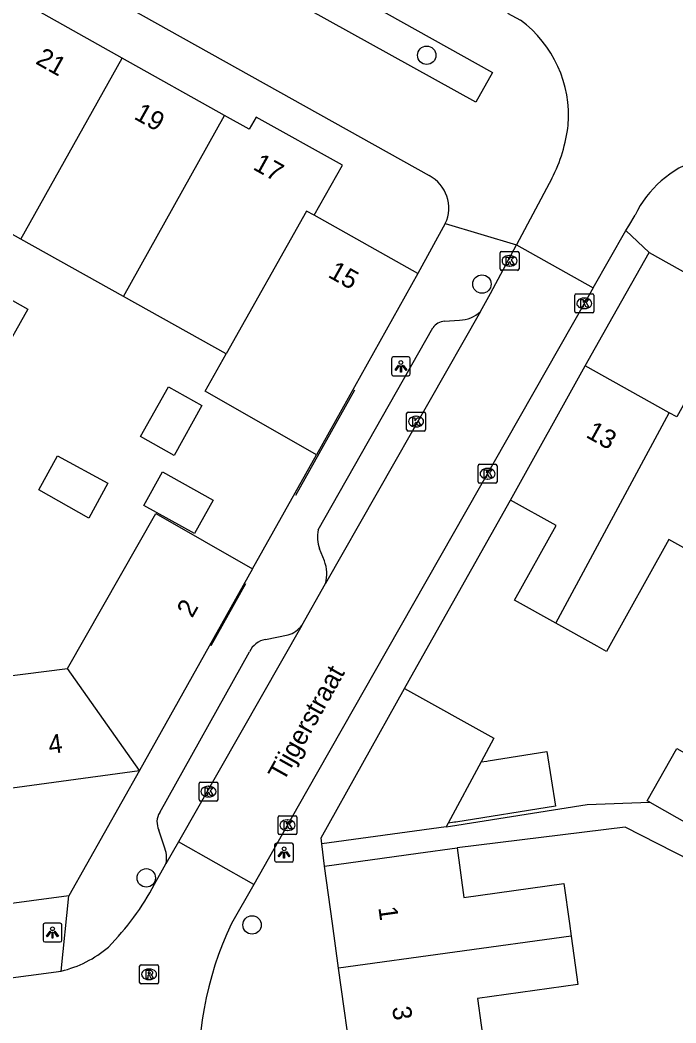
# Model space of a CAD drawing. Extents: x 163150 to 163546, y 380933 to 381635.
# Drawn here: x 163384.3 to 163419, y 381494.7 to 381547.9 of the extents above; entities that cross this region are included whole.
import ezdxf

# ---------------------------------------------------------------- set-up
doc = ezdxf.new("R2010")
doc.units = 0
for name, color, linetype in [('IMGEO_Boom', 7, 'Continuous'), ('IMGEO_Kolk', 7, 'Continuous'), ('IMGEO_Lichtpunt', 7, 'Continuous'), ('IMGEO_Muur', 7, 'Continuous'), ('IMGEO_Openbare_ruimte_label', 7, 'Continuous'), ('IMGEO_Pand', 7, 'Continuous'), ('IMGEO_Pand_nummerreeks', 7, 'Continuous'), ('IMGEO_Rijbaan_lokaal_open', 7, 'Continuous'), ('IMGEO_Rioolput', 7, 'Continuous'), ('IMGEO_Voetpad_open', 7, 'Continuous')]:
    doc.layers.add(name, color=color, linetype=linetype)

msp = doc.modelspace()

# ---------------------------------------------------------------- linework, layer by layer
at = {"layer": 'IMGEO_Boom'}
for centre in [(163405.837, 381545.994), (163408.762, 381533.873), (163390.984, 381502.417), (163396.588, 381499.924)]:
    msp.add_circle(centre, 0.489, dxfattribs=at)
at = {"layer": 'IMGEO_Kolk'}
for p, q in [((163409.724, 381534.676), (163409.724, 381535.528)), ((163409.799, 381535.602), (163410.651, 381535.602)), ((163410.212, 381535.382), (163410.237, 381535.382)), ((163410.725, 381535.528), (163410.725, 381534.676)), ((163410.651, 381534.602), (163409.799, 381534.602)), ((163410.235, 381534.822), (163410.21, 381534.822)), ((163413.683, 381532.426), (163413.683, 381533.278)), ((163413.758, 381533.352), (163414.61, 381533.352)), ((163414.171, 381533.132), (163414.196, 381533.132)), ((163414.684, 381533.278), (163414.684, 381532.426)), ((163414.194, 381532.572), (163414.169, 381532.572)), ((163414.61, 381532.352), (163413.758, 381532.352)), ((163404.772, 381526.162), (163404.772, 381527.014)), ((163404.847, 381527.088), (163405.699, 381527.088)), ((163405.26, 381526.868), (163405.285, 381526.868)), ((163405.773, 381527.014), (163405.773, 381526.162)), ((163405.699, 381526.088), (163404.847, 381526.088)), ((163405.283, 381526.308), (163405.258, 381526.308)), ((163408.561, 381523.401), (163408.561, 381524.253)), ((163408.636, 381524.327), (163409.488, 381524.327)), ((163409.049, 381524.107), (163409.074, 381524.107)), ((163409.562, 381524.253), (163409.562, 381523.401)), ((163409.072, 381523.547), (163409.047, 381523.547)), ((163409.488, 381523.327), (163408.636, 381523.327)), ((163393.856, 381507.487), (163394.708, 381507.487)), ((163393.781, 381506.561), (163393.781, 381507.413)), ((163394.269, 381507.267), (163394.294, 381507.267)), ((163394.782, 381507.413), (163394.782, 381506.561)), ((163394.708, 381506.487), (163393.856, 381506.487)), ((163394.292, 381506.707), (163394.267, 381506.707)), ((163397.961, 381504.782), (163397.961, 381505.634)), ((163398.036, 381505.708), (163398.888, 381505.708)), ((163398.449, 381505.488), (163398.474, 381505.488)), ((163398.962, 381505.634), (163398.962, 381504.782)), ((163398.472, 381504.928), (163398.447, 381504.928)), ((163398.888, 381504.708), (163398.036, 381504.708))]:
    msp.add_line(p, q, dxfattribs=at)
for points in [[(163409.724, 381534.676), (163409.724, 381535.528)], [(163409.799, 381535.602), (163410.651, 381535.602)], [(163410.045, 381535.302), (163410.168, 381535.302), (163410.168, 381535.151), (163410.298, 381535.302), (163410.462, 381535.302), (163410.316, 381535.151), (163410.469, 381534.902), (163410.317, 381534.902), (163410.232, 381535.066), (163410.168, 381534.999), (163410.168, 381534.902), (163410.045, 381534.902), (163410.045, 381535.302)], [(163410.725, 381535.528), (163410.725, 381534.676)], [(163410.651, 381534.602), (163409.799, 381534.602)], [(163413.683, 381532.426), (163413.683, 381533.278)], [(163413.758, 381533.352), (163414.61, 381533.352)], [(163414.004, 381533.052), (163414.127, 381533.052), (163414.127, 381532.901), (163414.257, 381533.052), (163414.421, 381533.052), (163414.275, 381532.901), (163414.428, 381532.652), (163414.276, 381532.652), (163414.191, 381532.816), (163414.127, 381532.749), (163414.127, 381532.652), (163414.004, 381532.652), (163414.004, 381533.052)], [(163414.684, 381533.278), (163414.684, 381532.426)], [(163414.61, 381532.352), (163413.758, 381532.352)], [(163404.772, 381526.162), (163404.772, 381527.014)], [(163404.847, 381527.088), (163405.699, 381527.088)], [(163405.093, 381526.788), (163405.216, 381526.788), (163405.216, 381526.637), (163405.346, 381526.788), (163405.51, 381526.788), (163405.364, 381526.637), (163405.517, 381526.388), (163405.365, 381526.388), (163405.28, 381526.552), (163405.216, 381526.485), (163405.216, 381526.388), (163405.093, 381526.388), (163405.093, 381526.788)], [(163405.773, 381527.014), (163405.773, 381526.162)], [(163405.699, 381526.088), (163404.847, 381526.088)], [(163408.561, 381523.401), (163408.561, 381524.253)], [(163408.636, 381524.327), (163409.488, 381524.327)], [(163408.882, 381524.027), (163409.005, 381524.027), (163409.005, 381523.876), (163409.135, 381524.027), (163409.299, 381524.027), (163409.153, 381523.876), (163409.306, 381523.627), (163409.154, 381523.627), (163409.069, 381523.791), (163409.005, 381523.724), (163409.005, 381523.627), (163408.882, 381523.627), (163408.882, 381524.027)], [(163409.562, 381524.253), (163409.562, 381523.401)], [(163409.488, 381523.327), (163408.636, 381523.327)], [(163393.856, 381507.487), (163394.708, 381507.487)], [(163393.781, 381506.561), (163393.781, 381507.413)], [(163394.102, 381507.187), (163394.225, 381507.187), (163394.225, 381507.036), (163394.355, 381507.187), (163394.519, 381507.187), (163394.373, 381507.036), (163394.526, 381506.787), (163394.374, 381506.787), (163394.289, 381506.951), (163394.225, 381506.884), (163394.225, 381506.787), (163394.102, 381506.787), (163394.102, 381507.187)], [(163394.782, 381507.413), (163394.782, 381506.561)], [(163394.708, 381506.487), (163393.856, 381506.487)], [(163397.961, 381504.782), (163397.961, 381505.634)], [(163398.036, 381505.708), (163398.888, 381505.708)], [(163398.282, 381505.408), (163398.405, 381505.408), (163398.405, 381505.257), (163398.535, 381505.408), (163398.699, 381505.408), (163398.553, 381505.257), (163398.706, 381505.008), (163398.554, 381505.008), (163398.469, 381505.172), (163398.405, 381505.105), (163398.405, 381505.008), (163398.282, 381505.008), (163398.282, 381505.408)], [(163398.962, 381505.634), (163398.962, 381504.782)], [(163398.888, 381504.708), (163398.036, 381504.708)]]:
    msp.add_lwpolyline(points, dxfattribs=at)
for centre, start, end in [((163409.801, 381535.526), 91.552, 178.448), ((163409.801, 381535.526), 91.552, 178.448), ((163410.649, 381535.526), 1.552, 88.448), ((163410.649, 381535.526), 1.552, 88.448), ((163409.801, 381534.678), 181.552, 268.448), ((163409.801, 381534.678), 181.552, 268.448), ((163410.649, 381534.678), 271.552, 358.448), ((163410.649, 381534.678), 271.552, 358.448), ((163413.76, 381533.276), 91.552, 178.448), ((163413.76, 381533.276), 91.552, 178.448), ((163414.608, 381533.276), 1.552, 88.448), ((163414.608, 381533.276), 1.552, 88.448), ((163413.76, 381532.428), 181.552, 268.448), ((163413.76, 381532.428), 181.552, 268.448), ((163414.608, 381532.428), 271.552, 358.448), ((163414.608, 381532.428), 271.552, 358.448), ((163404.849, 381527.012), 91.552, 178.448), ((163404.849, 381527.012), 91.552, 178.448), ((163405.697, 381527.012), 1.552, 88.448), ((163405.697, 381527.012), 1.552, 88.448), ((163404.849, 381526.164), 181.552, 268.448), ((163404.849, 381526.164), 181.552, 268.448), ((163405.697, 381526.164), 271.552, 358.448), ((163405.697, 381526.164), 271.552, 358.448), ((163408.638, 381524.251), 91.552, 178.448), ((163408.638, 381524.251), 91.552, 178.448), ((163409.486, 381524.251), 1.552, 88.448), ((163409.486, 381524.251), 1.552, 88.448), ((163408.638, 381523.403), 181.552, 268.448), ((163408.638, 381523.403), 181.552, 268.448), ((163409.486, 381523.403), 271.552, 358.448), ((163409.486, 381523.403), 271.552, 358.448), ((163393.858, 381507.411), 91.552, 178.448), ((163393.858, 381507.411), 91.552, 178.448), ((163394.706, 381507.411), 1.552, 88.448), ((163394.706, 381507.411), 1.552, 88.448), ((163393.858, 381506.563), 181.552, 268.448), ((163393.858, 381506.563), 181.552, 268.448), ((163394.706, 381506.563), 271.552, 358.448), ((163394.706, 381506.563), 271.552, 358.448), ((163398.038, 381505.632), 91.552, 178.448), ((163398.038, 381505.632), 91.552, 178.448), ((163398.886, 381505.632), 1.552, 88.448), ((163398.886, 381505.632), 1.552, 88.448), ((163398.038, 381504.784), 181.552, 268.448), ((163398.038, 381504.784), 181.552, 268.448), ((163398.886, 381504.784), 271.552, 358.448), ((163398.886, 381504.784), 271.552, 358.448)]:
    msp.add_arc(centre, 0.0765, start, end, dxfattribs=at)
for centre, major_axis, ratio, start_param, end_param in [((163410.211, 381535.102), (-0.387, 0.002), 0.722429, 4.712389, 7.853982), ((163410.236, 381535.102), (-0.39, 0.002), 0.717154, 1.570796, 4.712389), ((163414.17, 381532.852), (-0.387, 0.002), 0.722429, 4.712389, 7.853982), ((163414.195, 381532.852), (-0.39, 0.002), 0.717154, 1.570796, 4.712389), ((163405.259, 381526.588), (-0.387, 0.002), 0.722429, 4.712389, 7.853982), ((163405.284, 381526.588), (-0.39, 0.002), 0.717154, 1.570796, 4.712389), ((163409.048, 381523.827), (-0.387, 0.002), 0.722429, 4.712389, 7.853982), ((163409.073, 381523.827), (-0.39, 0.002), 0.717154, 1.570796, 4.712389), ((163394.268, 381506.987), (-0.387, 0.002), 0.722429, 4.712389, 7.853982), ((163394.293, 381506.987), (-0.39, 0.002), 0.717154, 1.570796, 4.712389), ((163398.448, 381505.208), (-0.387, 0.002), 0.722429, 4.712389, 7.853982), ((163398.473, 381505.208), (-0.39, 0.002), 0.717154, 1.570796, 4.712389)]:
    msp.add_ellipse(centre, major_axis=major_axis, ratio=ratio, start_param=start_param, end_param=end_param, dxfattribs=at)
at = {"layer": 'IMGEO_Lichtpunt'}
for p, q in [((163403.972, 381529.922), (163403.972, 381529.115)), ((163403.972, 381529.922), (163403.972, 381529.115)), ((163404.874, 381530.017), (163404.066, 381530.017)), ((163404.874, 381530.017), (163404.066, 381530.017)), ((163404.968, 381529.115), (163404.968, 381529.922)), ((163404.968, 381529.115), (163404.968, 381529.922)), ((163404.066, 381529.021), (163404.874, 381529.021)), ((163404.066, 381529.021), (163404.874, 381529.021)), ((163397.783, 381504.159), (163397.783, 381503.352)), ((163397.783, 381504.159), (163397.783, 381503.352)), ((163398.685, 381504.254), (163397.877, 381504.254)), ((163398.685, 381504.254), (163397.877, 381504.254)), ((163398.779, 381503.352), (163398.779, 381504.159)), ((163398.779, 381503.352), (163398.779, 381504.159)), ((163397.877, 381503.258), (163398.685, 381503.258)), ((163397.877, 381503.258), (163398.685, 381503.258)), ((163385.518, 381499.924), (163385.518, 381499.117)), ((163385.518, 381499.924), (163385.518, 381499.117)), ((163386.42, 381500.019), (163385.612, 381500.019)), ((163386.42, 381500.019), (163385.612, 381500.019)), ((163386.514, 381499.117), (163386.514, 381499.924)), ((163386.514, 381499.117), (163386.514, 381499.924)), ((163385.612, 381499.023), (163386.42, 381499.023)), ((163385.612, 381499.023), (163386.42, 381499.023))]:
    msp.add_line(p, q, dxfattribs=at)
for points in [[(163404.346, 381529.586), (163404.385, 381529.558), (163404.197, 381529.296), (163404.159, 381529.323), (163404.346, 381529.586)], [(163404.448, 381529.538), (163404.495, 381529.538), (163404.495, 381529.216), (163404.448, 381529.216), (163404.448, 381529.538)], [(163404.558, 381529.558), (163404.596, 381529.585), (163404.783, 381529.323), (163404.744, 381529.295), (163404.558, 381529.558)], [(163398.157, 381503.823), (163398.196, 381503.795), (163398.008, 381503.533), (163397.97, 381503.56), (163398.157, 381503.823)], [(163398.259, 381503.775), (163398.306, 381503.775), (163398.306, 381503.453), (163398.259, 381503.453), (163398.259, 381503.775)], [(163398.369, 381503.795), (163398.407, 381503.822), (163398.594, 381503.56), (163398.555, 381503.532), (163398.369, 381503.795)], [(163385.892, 381499.588), (163385.931, 381499.56), (163385.743, 381499.298), (163385.705, 381499.325), (163385.892, 381499.588)], [(163385.994, 381499.54), (163386.041, 381499.54), (163386.041, 381499.218), (163385.994, 381499.218), (163385.994, 381499.54)], [(163386.104, 381499.56), (163386.142, 381499.587), (163386.329, 381499.325), (163386.29, 381499.297), (163386.104, 381499.56)]]:
    msp.add_lwpolyline(points, dxfattribs=at)
for centre in [(163404.471, 381529.72), (163398.282, 381503.957), (163386.017, 381499.722)]:
    msp.add_circle(centre, 0.0994, dxfattribs=at)
for centre, start, end in [((163404.066, 381529.922), 90, 180), ((163404.066, 381529.922), 90, 180), ((163404.874, 381529.922), 0, 90), ((163404.874, 381529.922), 0, 90), ((163404.066, 381529.115), 180, 270), ((163404.066, 381529.115), 180, 270), ((163404.874, 381529.115), 270, 0), ((163404.874, 381529.115), 270, 360), ((163397.877, 381504.159), 90, 180), ((163397.877, 381504.159), 90, 180), ((163398.685, 381504.159), 0, 90), ((163398.685, 381504.159), 0, 90), ((163397.877, 381503.352), 180, 270), ((163397.877, 381503.352), 180, 270), ((163398.685, 381503.352), 270, 0), ((163398.685, 381503.352), 270, 360), ((163385.612, 381499.924), 90, 180), ((163385.612, 381499.924), 90, 180), ((163386.42, 381499.924), 0, 90), ((163386.42, 381499.924), 0, 90), ((163385.612, 381499.117), 180, 270), ((163385.612, 381499.117), 180, 270), ((163386.42, 381499.117), 270, 0), ((163386.42, 381499.117), 270, 360)]:
    msp.add_arc(centre, 0.0946, start, end, dxfattribs=at)
at = {"layer": 'IMGEO_Muur'}
for points in [[(163398.9, 381522.691), (163402.034, 381528.266)], [(163405.156, 381513.335), (163410.272, 381522.434)], [(163394.422, 381514.725), (163396.264, 381518.003)]]:
    msp.add_lwpolyline(points, dxfattribs=at)
at = {"layer": 'IMGEO_Pand'}
for points in [[(163389.698, 381545.85), (163384.263, 381548.895)], [(163384.335, 381536.26), (163389.698, 381545.85)], [(163395.133, 381542.804), (163389.698, 381545.85)], [(163389.772, 381533.219), (163395.133, 381542.804)], [(163399.878, 381537.517), (163401.373, 381540.169), (163396.812, 381542.714), (163396.436, 381542.073), (163395.133, 381542.804)], [(163384.335, 381536.26), (163378.897, 381539.301)], [(163399.878, 381537.517), (163399.474, 381537.743), (163395.21, 381530.178)], [(163405.373, 381534.442), (163399.878, 381537.517)], [(163389.772, 381533.219), (163384.335, 381536.26)], [(163405.373, 381534.442), (163399.995, 381524.821)], [(163382.946, 381533.542), (163384.705, 381532.549), (163383.23, 381529.937), (163381.471, 381530.93)], [(163395.21, 381530.178), (163389.772, 381533.219)], [(163399.995, 381524.821), (163394.095, 381528.2), (163395.21, 381530.178)], [(163410.272, 381522.434), (163414.231, 381529.537)], [(163418.679, 381527.058), (163414.231, 381529.537)], [(163425.443, 381526.737), (163420.55, 381529.464), (163419.083, 381526.833), (163418.679, 381527.058)], [(163392.157, 381528.422), (163393.933, 381527.438), (163392.466, 381524.79), (163390.677, 381525.803), (163392.157, 381528.422)], [(163412.675, 381515.904), (163418.679, 381527.058)], [(163386.277, 381524.781), (163388.941, 381523.333), (163387.936, 381521.476), (163385.288, 381522.981), (163386.277, 381524.781)], [(163390.856, 381522.148), (163391.845, 381523.923), (163394.528, 381522.435), (163393.543, 381520.66), (163390.856, 381522.148)], [(163412.675, 381515.904), (163410.492, 381517.121), (163412.7, 381521.08), (163410.272, 381522.434)], [(163386.81, 381513.506), (163391.494, 381521.713), (163396.616, 381518.793)], [(163421.229, 381518.91), (163418.659, 381520.343), (163415.352, 381514.411), (163414.86, 381514.686), (163412.675, 381515.904)], [(163396.616, 381518.793), (163390.622, 381508.099)], [(163378.437, 381512.446), (163386.81, 381513.506)], [(163390.622, 381508.099), (163386.81, 381513.506)], [(163400.279, 381504.213), (163400.246, 381504.532), (163404.666, 381512.456)], [(163404.666, 381512.456), (163409.399, 381509.817), (163408.72, 381508.556)], [(163408.72, 381508.556), (163409.018, 381508.603), (163409.088, 381508.615), (163412.202, 381509.113), (163412.665, 381506.223), (163407.37, 381505.375), (163407.307, 381505.365), (163407.203, 381505.348), (163406.974, 381505.312)], [(163417.656, 381506.427), (163417.521, 381506.503), (163419.091, 381509.276), (163421.419, 381507.957)], [(163408.72, 381508.556), (163406.974, 381505.312)], [(163379.644, 381502.906), (163382.408, 381503.275), (163381.921, 381506.929), (163390.622, 381508.099)], [(163417.656, 381506.427), (163419.867, 381505.174)], [(163406.872, 381505.122), (163400.279, 381504.213)], [(163406.974, 381505.312), (163406.872, 381505.122)], [(163400.424, 381503.043), (163405.378, 381503.726), (163407.444, 381504.011)], [(163407.444, 381504.011), (163407.806, 381501.386), (163413.097, 381502.115), (163413.393, 381500), (163413.486, 381499.333)], [(163401.169, 381497.642), (163400.844, 381500), (163400.424, 381503.043)], [(163413.486, 381499.333), (163401.169, 381497.642)], [(163413.486, 381499.333), (163413.844, 381496.769), (163408.52, 381496.035), (163408.91, 381493.202)], [(163401.915, 381492.238), (163401.169, 381497.642)]]:
    msp.add_lwpolyline(points, dxfattribs=at)
at = {"layer": 'IMGEO_Rijbaan_lokaal_open'}
for points in [[(163410.118, 381548.234), (163410.806, 381547.858)], [(163412.47, 381539.47), (163410.599, 381535.956)], [(163416.384, 381536.72), (163416.546, 381536.957), (163416.871, 381537.519)], [(163414.654, 381533.678), (163416.384, 381536.72)], [(163408.677, 381532.42), (163409.219, 381533.373), (163410.599, 381535.956)], [(163410.599, 381535.956), (163414.654, 381533.678)], [(163414.654, 381533.678), (163414.262, 381532.989), (163403.04, 381513.257), (163402.013, 381511.452), (163400.059, 381508.016), (163399.031, 381506.208), (163396.678, 381502.07)], [(163408.677, 381532.42), (163400.477, 381518.009)], [(163399.217, 381515.793), (163400.477, 381518.009)], [(163399.217, 381515.793), (163392.697, 381504.335)], [(163392.697, 381504.335), (163392.026, 381503.156)], [(163396.678, 381502.07), (163392.697, 381504.335)], [(163391.416, 381502.077), (163392.026, 381503.156)], [(163396.678, 381502.07), (163395.5, 381500)], [(163382.807, 381497.014), (163382.998, 381497.011), (163386.472, 381497.48)]]:
    msp.add_lwpolyline(points, dxfattribs=at)
for centre, radius, start, end in [((163407.016, 381542.779), 6.337, 355.6466, 53.2708), ((163404.639, 381543.411), 8.767, 333.2821, 352.7033), ((163422.009, 381535.048), 5.702, 61.4772, 154.3223), ((163378.756, 381508.8), 14.335, 315.5111, 332.0291), ((163411.836, 381492.225), 18.092, 154.5483, 184.6632), ((163385.108, 381503.273), 5.952, 283.2481, 310.6101)]:
    msp.add_arc(centre, radius, start, end, dxfattribs=at)
at = {"layer": 'IMGEO_Rioolput'}
for p, q in [((163390.631, 381496.88), (163390.631, 381497.732)), ((163390.706, 381497.806), (163391.558, 381497.806)), ((163391.119, 381497.586), (163391.144, 381497.586)), ((163391.632, 381497.732), (163391.632, 381496.88)), ((163391.142, 381497.026), (163391.117, 381497.026)), ((163391.558, 381496.806), (163390.706, 381496.806))]:
    msp.add_line(p, q, dxfattribs=at)
for points in [[(163390.631, 381496.88), (163390.631, 381497.732)], [(163390.706, 381497.806), (163391.558, 381497.806)], [(163391.22, 381497.504), (163390.968, 381497.506), (163390.968, 381497.106)], [(163391.146, 381497.425), (163391.092, 381497.425), (163391.092, 381497.344)], [(163391.632, 381497.732), (163391.632, 381496.88)], [(163390.968, 381497.106), (163391.092, 381497.106), (163391.092, 381497.268), (163391.103, 381497.268)], [(163391.092, 381497.344), (163391.144, 381497.344)], [(163391.15, 381497.239), (163391.221, 381497.106), (163391.361, 381497.106), (163391.296, 381497.232)], [(163391.558, 381496.806), (163390.706, 381496.806)]]:
    msp.add_lwpolyline(points, dxfattribs=at)
for centre, radius, start, end in [((163390.708, 381497.73), 0.0765, 91.552, 178.448), ((163390.708, 381497.73), 0.0765, 91.552, 178.448), ((163391.152, 381497.329), 0.0964, 77.0061, 93.1865), ((163391.166, 381497.386), 0.0378, 276.6634, 79.6772), ((163391.219, 381497.394), 0.109, 350.3612, 89.416), ((163391.556, 381497.73), 0.0765, 1.552, 88.448), ((163391.556, 381497.73), 0.0765, 1.552, 88.448), ((163390.708, 381496.882), 0.0765, 181.552, 268.448), ((163390.708, 381496.882), 0.0765, 181.552, 268.448), ((163391.102, 381497.215), 0.0533, 26.0293, 88.6989), ((163391.128, 381497.533), 0.19, 274.7715, 282.9687), ((163391.217, 381497.394), 0.112, 277.5842, 350.9817), ((163391.201, 381497.179), 0.108, 29.5134, 73.7905), ((163391.556, 381496.882), 0.0765, 271.552, 358.448), ((163391.556, 381496.882), 0.0765, 271.552, 358.448)]:
    msp.add_arc(centre, radius, start, end, dxfattribs=at)
for centre, major_axis, ratio, start_param, end_param in [((163391.118, 381497.306), (-0.387, 0.002), 0.722429, 4.712389, 7.853982), ((163391.143, 381497.306), (-0.39, 0.002), 0.717154, 1.570796, 4.712389)]:
    msp.add_ellipse(centre, major_axis=major_axis, ratio=ratio, start_param=start_param, end_param=end_param, dxfattribs=at)
at = {"layer": 'IMGEO_Voetpad_open'}
for points in [[(163297.645, 381600.322), (163371.092, 381559.098), (163405.961, 381539.624)], [(163392.587, 381554.436), (163409.323, 381545.083), (163408.442, 381543.507), (163391.704, 381552.793), (163392.587, 381554.436)], [(163406.822, 381537.075), (163405.373, 381534.442)], [(163406.822, 381537.075), (163410.599, 381535.956)], [(163417.612, 381535.547), (163416.384, 381536.72)], [(163414.231, 381529.537), (163415.715, 381532.175), (163417.612, 381535.547)], [(163417.612, 381535.547), (163450.218, 381517.299), (163454.104, 381515.141)], [(163406.779, 381531.908), (163407.579, 381531.958)], [(163400.091, 381520.848), (163406.154, 381531.56)], [(163396.616, 381518.793), (163399.995, 381524.821)], [(163404.666, 381512.456), (163405.156, 381513.335), (163410.272, 381522.434)], [(163400.416, 381519.211), (163400.164, 381519.848)], [(163397.3, 381515.05), (163398.491, 381515.293)], [(163391.695, 381505.878), (163396.445, 381514.395)], [(163390.622, 381508.099), (163386.878, 381501.46)], [(163406.872, 381505.122), (163407.094, 381505.153), (163414.331, 381506.299), (163417.656, 381506.427)], [(163391.925, 381504.1), (163391.651, 381504.952)], [(163422.267, 381503.814), (163421.576, 381502.441), (163416.346, 381505.106), (163407.444, 381504.011)], [(163400.424, 381503.043), (163400.279, 381504.213)], [(163386.878, 381501.46), (163323.846, 381493.024)], [(163386.472, 381497.48), (163386.878, 381501.46)]]:
    msp.add_lwpolyline(points, dxfattribs=at)
for centre, radius, start, end in [((163405.063, 381537.901), 1.943, 334.8576, 62.4702), ((163407.491, 381533.704), 1.748, 272.8965, 312.7428), ((163406.875, 381531), 0.913, 96.0582, 142.1599), ((163401.659, 381520.46), 1.615, 166.0949, 202.2555), ((163398.581, 381518.515), 1.963, 345.0495, 20.7609), ((163398.137, 381516.585), 1.339, 285.3429, 323.7679), ((163397.524, 381513.872), 1.199, 100.7741, 154.1361), ((163392.49, 381505.376), 0.941, 147.7537, 206.8055), ((163390.557, 381503.476), 1.503, 347.6991, 24.5148)]:
    msp.add_arc(centre, radius, start, end, dxfattribs=at)

# ---------------------------------------------------------------- texts
at = {"layer": 'IMGEO_Openbare_ruimte_label'}
msp.add_text('Tijgerstraat', height=1, rotation=60.7172, dxfattribs=at).set_placement((163398.252, 381507.467))
at = {"layer": 'IMGEO_Pand_nummerreeks'}
for s, rotation, p in [('21', 330.7333, (163385.069, 381545.578)), ('19', 330.7333, (163390.281, 381542.656)), ('17', 330.8364, (163396.585, 381539.977)), ('15', 330.7677, (163400.557, 381534.273)), ('13', 330.8678, (163414.216, 381525.79)), ('2', 60.7278, (163393.413, 381516.146)), ('4', 7.6604, (163385.861, 381508.972)), ('1', 277.8537, (163403.272, 381500.848)), ('3', 277.8598, (163404.001, 381495.557))]:
    msp.add_text(s, height=1, rotation=rotation, dxfattribs=at).set_placement(p)

doc.saveas('drawing.dxf')
